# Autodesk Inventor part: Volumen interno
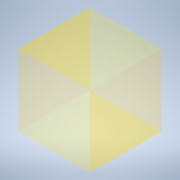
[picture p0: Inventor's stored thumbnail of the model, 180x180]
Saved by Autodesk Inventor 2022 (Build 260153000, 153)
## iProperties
Created: 2022-05
Part Number: Volumen interno
Material: Generic
Document SubType Name: Modeling
Designer: valen
Density: 1 g/cm^3
Appearance: Default
Author: valen
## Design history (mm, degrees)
sketch "Sketch1"
  geometry: L1 (-43.5, -43.5)-(43.5, -43.5); L2 (43.5, -43.5)-(43.5, 43.5); L3 (43.5, 43.5)-(-43.5, 43.5); L4 (-43.5, 43.5)-(-43.5, -43.5); L5 (-43.5, -43.5)-(43.5, 43.5); L6 (43.5, -43.5)-(-43.5, 43.5); 1 further point
  constraints: 12 end point, 2 midpoint, 2 parallel, 1 horizontal, 1 perpendicular
  dimensions: "d0" = 87 distance of L3.end L2.end; "d1" = 87 distance of L2.end L1.end
extrude_surface "ExtrusionSrf1" sketch "Sketch1" dims "d2" = 87, "d3" = 0
workplane "Work Plane1"
sketch "Sketch2"
  geometry: L1 (43.5, -43.5)-(-43.5, -43.5) reference; L2 (43.5, -43.5)-(43.5, 43.5) reference; L3 (-43.5, 43.5)-(43.5, 43.5); L4 (43.5, 43.5)-(43.5, -43.5); L5 (43.5, -43.5)-(-43.5, -43.5); L6 (-43.5, -43.5)-(-43.5, 43.5); L7 (-43.5, 43.5)-(43.5, -43.5); L8 (43.5, 43.5)-(-43.5, -43.5); 1 further point
  constraints: 12 end point, 2 midpoint, 2 parallel, 1 horizontal, 1 perpendicular
  dimensions: "d4" = 87 distance of L1.start L5.end (derived); "d5" = 87 distance of L3.end L1.start (derived)
extrude_surface "ExtrusionSrf2" sketch "Sketch2" dims "d6" = 87, "d7" = 0
body "Srf1"
body "Srf2"
